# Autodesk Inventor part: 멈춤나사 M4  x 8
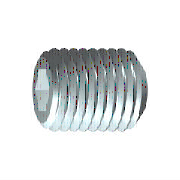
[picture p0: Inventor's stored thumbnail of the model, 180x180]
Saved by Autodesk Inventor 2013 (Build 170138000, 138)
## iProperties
IsCustomPart: 1
Created: 2012-02
Part Number: 멈춤나사 M4  x 8
Material: 강철, 연강
Description: 6각 소켓 머리 없는 멈춤 나사
Document SubType Name: Modeling
Standard: KS B 1028
Designer: mduedu
Standards Organization: KS
Language: ko-KR
Size Designation: 납작점M4x5
Categories: <MemberInstance><Categories><Category DisplayName="조임쇠" InternalName="e4da775c-781d-43d5-af7c-5136215cf5a6" Mnemonic="FSTN"><Category DisplayName="볼트" InternalN
Density: 7.86 g/cm^3
Mass: 0.698078 g
Surface Area: 1.37125 cm^2
Volume: 0.088814 cm^3
Author: mduedu
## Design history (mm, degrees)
sketch "스케치1"
  geometry: L1 (0, 0)-(4.833, 0); L2 (8, 1.155)-(8, 2); L3 (8, 2)-(0, 2); L4 (8, 1.155)-(5.5, 1.155); L5 (5.5, 1.155)-(4.833, 0); L6 (0, -0.4)-(0, 2.4) reference; L7 (0, 2)-(0, 0)
  constraints: 13 end point, 3 parallel, 1 collinear, 1 perpendicular, 1 point on line
  dimensions: "d0" = 2.5 distance of L2.start L4.end (= INTI); "d1" = 60 deg angle of L5 L1; "d2" = 4 diameter of L3 L1 (= NND); "d3" = 2.3094 diameter of L4 L1 (= 1.1547 x SW); "d5" = 8 distance from line of L2 L3.end (= NLG)
revolve "본체" sketch "스케치1" stored, may be unused: angle "d6" = 90 deg
sketch "스케치2"
  geometry: L1 (-0.577, 1)-(0.577, 1); L2 (0.577, 1)-(1.155, 0); L3 (1.155, 0)-(0.577, -1); L4 (0.577, -1)-(-0.577, -1); L5 (-0.577, -1)-(-1.155, 0); L6 (-1.155, 0)-(-0.577, 1); A1 r 1.155 centre (0, 0) between (-0.577, 1) and (0.577, 1) reference; 2 further points
  constraints: 12 end point, 2 point on circle, 1 coincident, 1 horizontal, 11 other
extrude "슬롯" join sketch "스케치2" taper "d9" = 0 deg; stored distance "d21" = 10
workaxis "Work Axis1"
workplane "Work Plane1"
body "Solid1"
chamfer "모따기1" distance "d7" = 0.42941 (= -0.5 x GD1 + 0.5 x NND); stored, may be unused: angle "d8" = 45 deg (= FAWI), second distance "d29" = 0.42941 (= -0.5 x GD1 + 0.5 x NND)
feature "스레드" dims "d11" = 8 (= NLG), "d12" = 0
chamfer "모따기2" distance "d13" = 0.42941 (= -0.5 x GD1 + 0.5 x NND); stored, may be unused: angle "d14" = 45 deg (= FAWI), second distance "d30" = 0.42941 (= -0.5 x GD1 + 0.5 x NND)
other parameters: "NND" = 4 [user parameter; used in 5 equation terms], "NLG" = 8 [user parameter; used in 2 equation terms], "INTI" = 2.5 [user parameter; used in 1 equation term], "FAWI" = 45 deg [user parameter; used in 2 equation terms], "SW" = 2 [user parameter; used in 2 equation terms], "GD1" = 3.14117 (= THREADDIA - 1.2269 x PTC) [user parameter; used in 4 equation terms], "d4" = 0, "FAWI1" = 45 deg [user parameter], "d15" = 0, "d31" = 0, "GUL" = 0.42941 (= 0.61345 x PTC) [user parameter], "SPD" = 2.5 [user parameter], "TPU" = 14.28571 (computed from PTC) [user parameter], "TOA" = 30 deg [user parameter], "THREADDIA" = 4 [user parameter; used in 1 equation term], "PTC" = 0.7 [user parameter; used in 4 equation terms], "GAL" = 0.42941 (= 0.61345 x PTC) [user parameter], "E0" = 2.31 (= 1.155 x SW) [user parameter]
